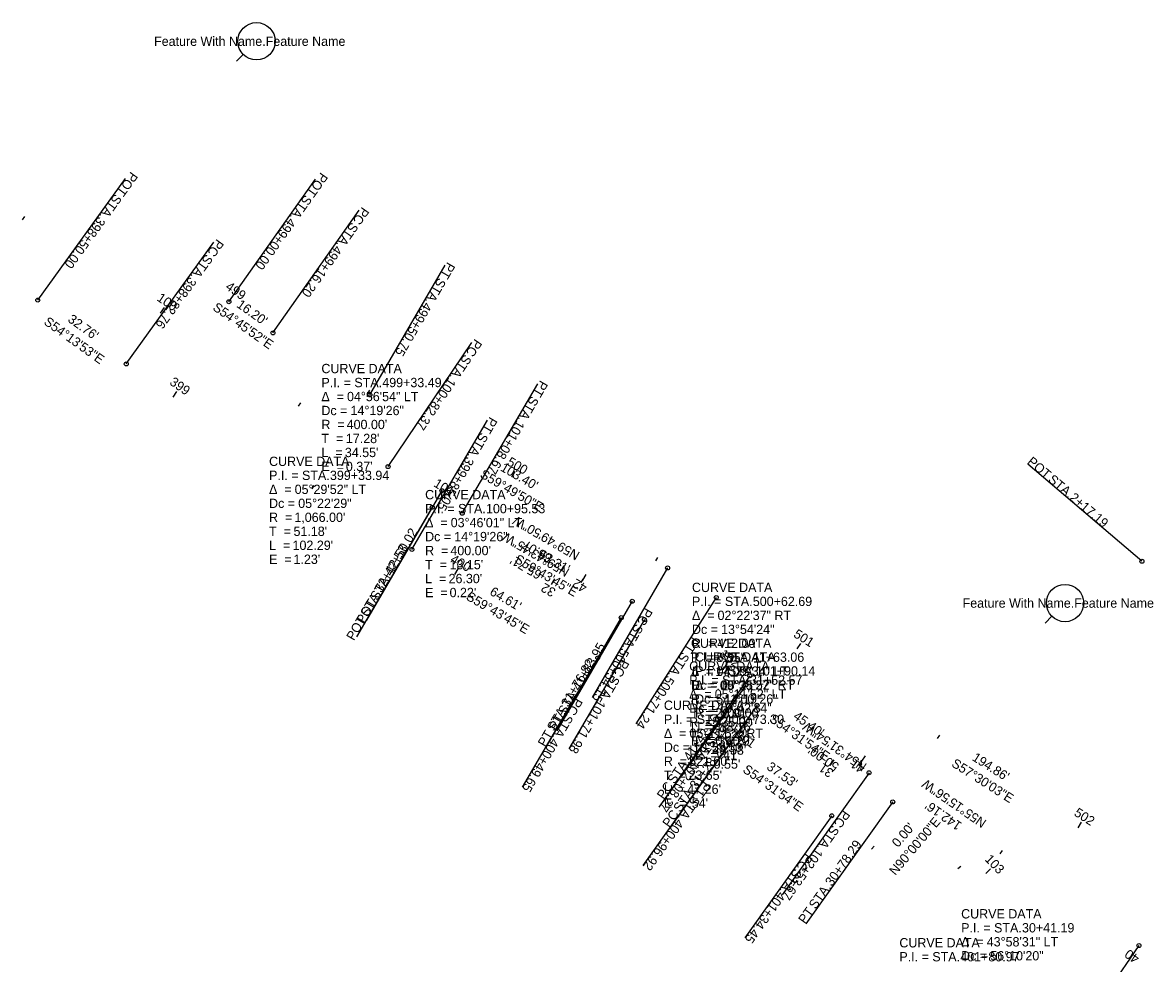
# Model space of a CAD drawing. Extents: x 1600023 to 1602131, y 285824 to 287284.
# Drawn here: x 1600662.8 to 1601002.3, y 286757.4 to 287039.9 of the extents above; entities that cross this region are included whole.
import ezdxf

# ---------------------------------------------------------------- set-up
doc = ezdxf.new("R2010")
doc.units = 0
for name, color, linetype in [('_CIVIL_CONSTRUCTION', 7, 'Continuous'), ('Default', 7, 'Continuous'), ('GE_P_Alignment', 7, 'Continuous'), ('PF_P_Grade_Line', 7, 'Continuous'), ('PF_X_Ground_Line', 7, 'Continuous'), ('PV_P_Curb', 7, 'Continuous'), ('SC_Scratch6', 7, 'Continuous'), ('SC_Scratch8', 7, 'Continuous')]:
    doc.layers.add(name, color=color, linetype=linetype)

msp = doc.modelspace()

# ---------------------------------------------------------------- linework, layer by layer
at = {"layer": '_CIVIL_CONSTRUCTION'}
for p, q in [((1600772.53, 286906.56), (1600797.72, 286943.85)), ((1600794.79, 286892.56), (1600817.48, 286931.43)), ((1600998.84, 286878.14), (1600964.55, 286907.28)), ((1600849.47, 286860.65), (1600826.79, 286821.79)), ((1600879.94, 286840.96), (1600853.82, 286804.31)), ((1600916.91, 286814.62), (1600890.8, 286777.97))]:
    msp.add_line(p, q, dxfattribs=at)
for centre in [(1600772.53, 286906.56), (1600794.79, 286892.56), (1600998.84, 286878.14), (1600849.47, 286860.65), (1600879.94, 286840.96), (1600916.91, 286814.62)]:
    msp.add_circle(centre, 0.6, dxfattribs=at)
at = {"layer": 'Default'}
for p, q in [((1600667.38, 286956.56), (1600693.68, 286993.07)), ((1600724.75, 286956.08), (1600750.72, 286992.84)), ((1600737.99, 286946.73), (1600763.88, 286983.54)), ((1600693.96, 286937.41), (1600720.26, 286973.92)), ((1600767.07, 286928.11), (1600789.69, 286967.01)), ((1600724.75, 286956.08), (1600725.91, 286957.72)), ((1600708.03, 286927.45), (1600709.17, 286929.09)), ((1600766.42, 286928.48), (1600767.03, 286929.52)), ((1600779.69, 286881.69), (1600802.38, 286920.56)), ((1600809.65, 286903.36), (1600810.65, 286905.08)), ((1600749.72, 286899.85), (1600750.36, 286900.87)), ((1600788.7, 286899.34), (1600766.09, 286860.43)), ((1600788.72, 286899.33), (1600788.12, 286898.29)), ((1600785.79, 286894.34), (1600763.11, 286855.48)), ((1600852.88, 286878.23), (1600853.48, 286879.26)), ((1600792.61, 286874.16), (1600793.61, 286875.88)), ((1600831.95, 286874.2), (1600830.94, 286872.47)), ((1600856.46, 286876.14), (1600833.85, 286837.24)), ((1600822.53, 286872.9), (1600821.52, 286871.18)), ((1600871.06, 286867.25), (1600846.88, 286829.3)), ((1600845.82, 286866.13), (1600823.21, 286827.23)), ((1600842.55, 286861.22), (1600819.86, 286822.35)), ((1600895.31, 286851.8), (1600896.39, 286853.48)), ((1600835.79, 286848.95), (1600836.39, 286849.99)), ((1600835.49, 286849.13), (1600812.81, 286810.26)), ((1600865.36, 286847.12), (1600864.71, 286846.12)), ((1600874.62, 286848.16), (1600873.95, 286847.17)), ((1600881.11, 286843.76), (1600855.56, 286806.71)), ((1600883.3, 286834.89), (1600857.19, 286798.24)), ((1600937.48, 286824.93), (1600938.13, 286825.94)), ((1600875.17, 286823.48), (1600849.06, 286786.83)), ((1600877.68, 286821.7), (1600878.84, 286823.32)), ((1600915.75, 286819.74), (1600914.61, 286818.09)), ((1600906.33, 286818.47), (1600905.17, 286816.84)), ((1600924.02, 286805.87), (1600897.91, 286769.22)), ((1600905.74, 286801.71), (1600879.63, 286765.06)), ((1600979.65, 286798.07), (1600980.73, 286799.75)), ((1600917.63, 286791.71), (1600918.47, 286792.56)), ((1600956.84, 286791.25), (1600956.16, 286790.26)), ((1600944.5, 286786.5), (1600943.56, 286785.75)), ((1600997.93, 286762.76), (1600972.29, 286725.78)), ((1600997.93, 286762.76), (1600996.79, 286761.12))]:
    msp.add_line(p, q, dxfattribs=at)
for centre in [(1600667.38, 286956.56), (1600724.75, 286956.08), (1600737.99, 286946.73), (1600693.96, 286937.41), (1600767.07, 286928.11), (1600788.7, 286899.34), (1600785.79, 286894.34), (1600779.69, 286881.69), (1600856.46, 286876.14), (1600845.82, 286866.13), (1600871.06, 286867.25), (1600842.55, 286861.22), (1600835.49, 286849.13), (1600881.11, 286843.76), (1600883.3, 286834.89), (1600875.17, 286823.48), (1600924.02, 286805.87), (1600905.74, 286801.71), (1600997.93, 286762.76)]:
    msp.add_circle(centre, 0.6, dxfattribs=at)
at = {"layer": 'PV_P_Curb'}
for centre in [(1600733.05, 287034.3), (1600975.75, 286865.59)]:
    msp.add_circle(centre, 5.6, dxfattribs=at)
at = {"layer": 'SC_Scratch6'}
for p, q in [((1600662.84, 286980.65), (1600663.51, 286981.65)), ((1600704.27, 286952.66), (1600705.39, 286954.32)), ((1600745.7, 286924.68), (1600746.38, 286925.67)), ((1600787.35, 286897.02), (1600788.4, 286898.72)), ((1600830.49, 286871.73), (1600831.09, 286872.77)), ((1600873.15, 286845.69), (1600874.28, 286847.34)), ((1600913.92, 286816.75), (1600914.62, 286817.73)), ((1600951.95, 286784.4), (1600953.39, 286785.79))]:
    msp.add_line(p, q, dxfattribs=at)
at = {"layer": 'SC_Scratch8'}
for p, q in [((1600727.05, 287028.3), (1600729.09, 287030.34)), ((1600969.75, 286859.59), (1600971.79, 286861.63))]:
    msp.add_line(p, q, dxfattribs=at)
for points in [[(1600727.05, 287028.3), (1600727.75, 287029.01), (1600727.75, 287029.01)], [(1600969.75, 286859.59), (1600970.45, 286860.29), (1600970.45, 286860.29)]]:
    msp.add_lwpolyline(points, close=True, dxfattribs=at)

# ---------------------------------------------------------------- texts
at = {"layer": '_CIVIL_CONSTRUCTION'}
for s, rotation, p in [('PC', 235.9623, (1600798.63, 286945.12)), (' STA. ', 235.9623, (1600796.06, 286941.32)), ('100+82.37', 235.9623, (1600790.77, 286933.49)), ('PT', 239.7293, (1600818.26, 286932.68)), (' STA. ', 239.7293, (1600816.03, 286928.87)), ('101+08.67', 239.7293, (1600811.27, 286920.71)), ('POT', 319.6453, (1600964.17, 286907.66)), (' STA. ', 319.6453, (1600969.66, 286902.99)), ('2+17.19', 319.6453, (1600976.86, 286896.87)), ('PC', 239.7293, (1600842.69, 286848.95)), (' STA. ', 239.7293, (1600840.38, 286844.99)), ('101+71.98', 239.7293, (1600835.61, 286836.83)), ('PT', 234.5316, (1600872.12, 286829.92)), (' STA. ', 234.5316, (1600869.56, 286826.33)), ('102+08.27', 234.5316, (1600864.08, 286818.63)), ('PC', 234.5316, (1600909.15, 286803.65)), (' STA. ', 234.5316, (1600906.49, 286799.92)), ('102+53.67', 234.5316, (1600901, 286792.22))]:
    msp.add_text(s, height=2.8, rotation=rotation, dxfattribs=at).set_placement(p)
at = {"layer": 'Default'}
for s, rotation, p in [('POT', 234.2314, (1600695.35, 286995.32)), ('POT', 234.7644, (1600752.37, 286995.1)), (' STA. ', 234.2314, (1600691.14, 286989.48)), (' STA. ', 234.7644, (1600748.21, 286989.22)), ('PC', 234.8822, (1600764.77, 286984.74)), ('398+50.00', 234.2314, (1600685.62, 286981.81)), ('499+00.00', 234.7644, (1600742.76, 286981.5)), (' STA. ', 234.8822, (1600762.13, 286980.99)), ('PC', 234.2314, (1600721.17, 286975.12)), ('499+16.20', 234.8822, (1600756.69, 286973.26)), (' STA. ', 234.2314, (1600718.49, 286971.4)), ('PT', 239.8305, (1600790.41, 286968.17)), ('398+82.76', 234.2314, (1600712.97, 286963.73)), ('499', 324.7644, (1600723.49, 286960.04)), (' STA. ', 239.8305, (1600788.19, 286964.35)), ('S54°45\'52"E', 324.7644, (1600719.67, 286953.8)), ("16.20'", 324.7644, (1600726.85, 286954.65)), ('499+50.75', 239.8305, (1600783.44, 286956.18)), ('S54°13\'53"E', 324.2314, (1600668.99, 286949.49)), ("32.76'", 324.2314, (1600676.18, 286950.27)), ('399', 325.1582, (1600706.73, 286931.4)), ('PT', 239.7293, (1600803.1, 286921.71)), (' STA. ', 239.7293, (1600800.87, 286917.9)), ('399+85.05', 239.7293, (1600796.11, 286909.74)), ("103.40'", 329.8305, (1600806.01, 286905.52)), ('500', 329.8305, (1600808.01, 286907.2)), ('S59°49\'50"E', 329.8305, (1600799.9, 286903.47)), ('N59°49\'50"W', 149.8305, (1600830.32, 286880.7)), ('42+50.02', 59.8305, (1600773.61, 286873.46)), ('N59°43\'45"W', 149.7293, (1600827.23, 286875.72)), ("66.07'", 149.8305, (1600822.05, 286879.9)), ('32+42.53', 59.7293, (1600770.66, 286868.49)), ('400', 329.7293, (1600790.98, 286878)), ("65.71'", 149.7293, (1600818.95, 286874.94)), (' STA. ', 59.8305, (1600768.86, 286865.28)), ("64.61'", 329.7293, (1600802.81, 286868.25)), ('32', 149.7293, (1600823.13, 286869.65)), ('42', 149.8305, (1600832.56, 286870.95)), ('POT', 59.8305, (1600765.24, 286859.06)), (' STA. ', 59.7293, (1600765.89, 286860.33)), ('S59°43\'45"E', 329.7293, (1600795.72, 286866.78)), ('PC', 239.8305, (1600849.69, 286864.41)), ('POT', 59.7293, (1600762.26, 286854.11)), (' STA. ', 239.8305, (1600847.38, 286860.44)), ('501', 327.5008, (1600894, 286855.6)), ('41+83.95', 59.8305, (1600830.02, 286839.03)), ('PT', 237.5008, (1600863.75, 286855.7)), ('500+54.15', 239.8305, (1600842.63, 286852.27)), (' STA. ', 237.5008, (1600861.37, 286851.98)), ('31+76.82', 59.7293, (1600826.71, 286834.16)), ('500+71.24', 237.5008, (1600856.3, 286844)), (' STA. ', 59.8305, (1600825.27, 286830.85)), ('PC', 239.7293, (1600828.7, 286837.4)), (' STA. ', 59.7293, (1600821.94, 286826)), ('PT', 59.8305, (1600823.05, 286827.04)), (' STA. ', 239.7293, (1600826.38, 286833.44)), ('41+42.16', 55.4065, (1600863.27, 286817.98)), ('N54°31\'54"W', 144.5316, (1600916.47, 286817.14)), ('PT', 59.7293, (1600819.72, 286822.18)), ('401', 324.5316, (1600876.57, 286825.56)), ('400+49.65', 239.7293, (1600821.62, 286825.28)), ('31+28.29', 54.5316, (1600865.09, 286809.41)), ("50.00'", 144.5316, (1600908.16, 286817.12)), ('41', 145.2657, (1600916, 286816.53)), ('S57°30\'03"E', 327.5008, (1600941.42, 286816.73)), ("194.86'", 327.5008, (1600947.62, 286818.53)), (' STA. ', 55.4065, (1600857.91, 286810.2)), ('S54°31\'54"E', 324.5316, (1600878.76, 286815.03)), ("37.53'", 324.5316, (1600885.95, 286815.86)), ('31', 144.5316, (1600906.54, 286815.26)), ('PT', 234.5316, (1600867.28, 286812.33)), ('N55°15\'56"W', 145.2657, (1600952.38, 286800.19)), ('PC', 55.4065, (1600855.31, 286806.42)), (' STA. ', 54.5316, (1600859.61, 286801.71)), (' STA. ', 234.5316, (1600864.72, 286808.74)), ("142.16'", 145.2657, (1600944.99, 286799.42)), ('PC', 54.5316, (1600856.95, 286797.98)), ('502', 327.5008, (1600978.23, 286801.94)), ('400+96.92', 234.5316, (1600859.23, 286801.04)), ('30+78.29', 54.5316, (1600905.77, 286780.33)), ('PC', 234.5316, (1600897.91, 286790.64)), (' STA. ', 234.5316, (1600895.25, 286786.91)), ('401+34.45', 234.5316, (1600889.77, 286779.21)), (' STA. ', 54.5316, (1600900.28, 286772.63)), ('PT', 54.5316, (1600897.72, 286769.04)), ('40', 145.2657, (1600998.34, 286759.44))]:
    msp.add_text(s, height=2.8, rotation=rotation, dxfattribs=at).set_placement(p)
for s, p in [('CURVE DATA', (1600752.53, 286934.62)), ('P.I. = STA. ', (1600752.53, 286930.42)), ('499+33.49', (1600770.8, 286930.42)), ('Δ  = ', (1600752.53, 286926.22)), ('04°56\'54" LT', (1600760.21, 286926.22)), ('Dc = ', (1600752.53, 286922.02)), ('14°19\'26"', (1600761.27, 286922.02)), ('R  = ', (1600752.53, 286917.82)), ("400.00'", (1600760.11, 286917.82)), ('T  = ', (1600752.53, 286913.62)), ("17.28'", (1600759.87, 286913.62)), ('L  = ', (1600752.53, 286909.42)), ("34.55'", (1600759.57, 286909.42)), ('CURVE DATA', (1600736.82, 286906.75)), ('E  = ', (1600752.53, 286905.22)), ("0.37'", (1600759.87, 286905.22)), ('P.I. = STA. ', (1600736.82, 286902.55)), ('399+33.94', (1600755.09, 286902.55)), ('Δ  = ', (1600736.82, 286898.35)), ('05°29\'52" LT', (1600744.5, 286898.35)), ('Dc = ', (1600736.82, 286894.15)), ('05°22\'29"', (1600745.56, 286894.15)), ('R  = ', (1600736.82, 286889.95)), ("1,066.00'", (1600744.41, 286889.95)), ('T  = ', (1600736.82, 286885.75)), ("51.18'", (1600744.16, 286885.75)), ('L  = ', (1600736.82, 286881.55)), ("102.29'", (1600743.87, 286881.55)), ('E  = ', (1600736.82, 286877.35)), ("1.23'", (1600744.16, 286877.35)), ('CURVE DATA', (1600863.76, 286868.9)), ('P.I. = STA. ', (1600863.76, 286864.7)), ('500+62.69', (1600882.03, 286864.7)), ('Δ  = ', (1600863.76, 286860.5)), ('02°22\'37" RT', (1600871.44, 286860.5)), ('Dc = ', (1600863.76, 286856.3)), ('13°54\'24"', (1600872.5, 286856.3)), ('CURVE DATA', (1600863.46, 286852.15)), ('R  = ', (1600863.76, 286852.1)), ("412.00'", (1600871.34, 286852.1)), ('P.I. = STA. ', (1600863.46, 286847.95)), ('T  = ', (1600863.76, 286847.9)), ("8.55'", (1600871.1, 286847.9)), ('41+63.06', (1600881.73, 286847.95)), ('CURVE DATA', (1600862.92, 286845.25)), ('Δ  = ', (1600863.46, 286843.75)), ('L  = ', (1600863.76, 286843.7)), ("17.09'", (1600870.8, 286843.7)), ('04°25\'34" LT', (1600871.14, 286843.75)), ('P.I. = STA. ', (1600862.92, 286841.05)), ('31+52.57', (1600881.19, 286841.05)), ('Δ  = ', (1600862.92, 286836.85)), ('Dc = ', (1600863.46, 286839.55)), ('E  = ', (1600863.76, 286839.5)), ('05°11\'52" LT', (1600870.6, 286836.85)), (".09'", (1600871.1, 286839.5)), ('10°35\'27"', (1600872.2, 286839.55)), ('CURVE DATA', (1600855.33, 286833.51)), ('R  = ', (1600863.46, 286835.35)), ("541.00'", (1600871.05, 286835.35)), ('Dc = ', (1600862.92, 286832.65)), ('T  = ', (1600863.46, 286831.15)), ("20.91'", (1600870.8, 286831.15)), ('10°42\'34"', (1600871.66, 286832.65)), ('P.I. = STA. ', (1600855.33, 286829.31)), ('R  = ', (1600862.92, 286828.45)), ('L  = ', (1600863.46, 286826.95)), ("41.79'", (1600870.51, 286826.95)), ("535.00'", (1600870.5, 286828.45)), ('400+73.30', (1600873.6, 286829.31)), ('Δ  = ', (1600855.33, 286825.11)), ('T  = ', (1600862.92, 286824.25)), ('05°11\'52" RT', (1600863.01, 286825.11)), ('E  = ', (1600863.46, 286822.75)), ("24.28'", (1600870.26, 286824.25)), ("0.40'", (1600870.81, 286822.75)), ('Dc = ', (1600855.33, 286820.91)), ('L  = ', (1600862.92, 286820.05)), ('10°59\'50"', (1600864.07, 286820.91)), ("48.53'", (1600869.96, 286820.05)), ('R  = ', (1600855.33, 286816.71)), ("521.00'", (1600862.91, 286816.71)), ("0.55'", (1600870.26, 286815.85)), ('T  = ', (1600855.33, 286812.51)), ("23.65'", (1600862.67, 286812.51)), ('E  = ', (1600862.92, 286815.85)), ('L  = ', (1600855.33, 286808.31)), ("47.26'", (1600862.37, 286808.31)), ('E  = ', (1600855.33, 286804.11)), (".54'", (1600862.67, 286804.11)), ('CURVE DATA', (1600944.56, 286770.88)), ('P.I. = STA. ', (1600944.56, 286766.68)), ('30+41.19', (1600962.83, 286766.68)), ('CURVE DATA', (1600926.02, 286762.19)), ('Δ  = ', (1600944.56, 286762.48)), ('43°58\'31" LT', (1600952.24, 286762.48)), ('Dc = ', (1600944.56, 286758.28)), ('56°10\'20"', (1600953.3, 286758.28)), ('P.I. = STA. ', (1600926.02, 286757.99)), ('401+80.97', (1600944.29, 286757.99))]:
    msp.add_text(s, height=2.8, dxfattribs=at).set_placement(p)
at = {"layer": 'GE_P_Alignment'}
for s, rotation, p in [('S59°43\'45"E', 329.7293, (1600810.26, 286877.98)), ('S54°31\'54"E', 324.5316, (1600886.73, 286830.23)), ('N90°00\'00"E', 49.6453, (1600924.83, 286783.62))]:
    msp.add_text(s, height=2.8, rotation=rotation, dxfattribs=at).set_placement(p)
at = {"layer": 'PF_P_Grade_Line'}
for s, rotation, p in [("63.31'", 329.7293, (1600817.35, 286879.45)), ("45.40'", 324.5316, (1600893.92, 286831.05)), ("0.00'", 49.6453, (1600925.62, 286792.03))]:
    msp.add_text(s, height=2.8, rotation=rotation, dxfattribs=at).set_placement(p)
at = {"layer": 'PF_X_Ground_Line'}
for s, p in [('CURVE DATA', (1600783.66, 286896.76)), ('P.I. = STA. ', (1600783.66, 286892.56)), ('100+95.53', (1600801.93, 286892.56)), ('Δ  = ', (1600783.66, 286888.36)), ('03°46\'01" LT', (1600791.34, 286888.36)), ('Dc = ', (1600783.66, 286884.16)), ('14°19\'26"', (1600792.4, 286884.16)), ('R  = ', (1600783.66, 286879.96)), ("400.00'", (1600791.24, 286879.96)), ('T  = ', (1600783.66, 286875.76)), ("13.15'", (1600791, 286875.76)), ('L  = ', (1600783.66, 286871.56)), ("26.30'", (1600790.7, 286871.56)), ('E  = ', (1600783.66, 286867.36)), ("0.22'", (1600791, 286867.36)), ('CURVE DATA', (1600864.7, 286848.01)), ('P.I. = STA. ', (1600864.7, 286843.81)), ('101+90.14', (1600882.97, 286843.81)), ('Δ  = ', (1600864.7, 286839.61)), ('05°11\'52" RT', (1600872.38, 286839.61)), ('Dc = ', (1600864.7, 286835.41)), ('14°19\'26"', (1600873.44, 286835.41)), ('R  = ', (1600864.7, 286831.21)), ("400.00'", (1600872.28, 286831.21)), ('T  = ', (1600864.7, 286827.01)), ("18.16'", (1600872.04, 286827.01)), ('L  = ', (1600864.7, 286822.81)), ("36.29'", (1600871.74, 286822.81)), ('E  = ', (1600864.7, 286818.61)), (".41'", (1600872.04, 286818.61))]:
    msp.add_text(s, height=2.8, dxfattribs=at).set_placement(p)
at = {"layer": 'PV_P_Curb'}
for p in [(1600702.3, 287032.9), (1600945, 286864.19)]:
    msp.add_text('Feature With Name.Feature Name', height=2.8, dxfattribs=at).set_placement(p)
at = {"layer": 'SC_Scratch6'}
for s, rotation, p in [('100', 325.9623, (1600702.9, 286956.61)), ('101', 328.4871, (1600785.97, 286900.79)), ('102', 325.7158, (1600871.85, 286849.6)), ('103', 313.9131, (1600951.48, 286788.49))]:
    msp.add_text(s, height=2.8, rotation=rotation, dxfattribs=at).set_placement(p)

doc.saveas('drawing.dxf')
